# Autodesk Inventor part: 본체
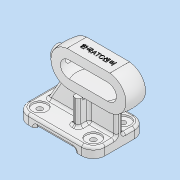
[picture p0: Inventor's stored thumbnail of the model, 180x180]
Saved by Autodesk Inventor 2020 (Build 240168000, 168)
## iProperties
Created: 2025-01
Part Number: 본체
Material: 알루미늄 6061
Document SubType Name: Modeling
Designer: 1강의실14
Density: 2.7 g/cm^3
Appearance: 알루미늄 - 평지
Mass: 359.313 g
Surface Area: 341.872 cm^2
Volume: 133.079 cm^3
Author: 1강의실14
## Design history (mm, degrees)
sketch "스케치1"
  geometry: L1 (-26, 21)-(26, 21); L2 (26, 21)-(26, -21); L3 (26, -21)-(-26, -21); L4 (-26, -21)-(-26, 21); L5 (-26, 10)-(26, 10); L6 (-26, -10)-(26, -10); L7 (0, -29.4)-(0, 29.4) reference; A1 r 21 centre (26, 0) between (26, -21) and (26, 21); A2 r 21 centre (-26, 0) between (-26, 21) and (-26, -21); A3 r 10 centre (-26, 0) between (-26, 10) and (-26, -10); A4 r 10 centre (26, 0) between (26, -10) and (26, 10); 1 further point
  constraints: 12 end point, 8 point on circle, 4 centre point, 4 point on line, 2 coincident, 2 parallel, 1 horizontal, 1 perpendicular
  dimensions: "d0" = 52 distance between parallel lines of L2 L4; "d1" = 42 distance between parallel lines of L3 L1; "d2" = 21 distance from line of point (0, 0) L1; "d3" = 26 distance from line of L4 point (0, 0); "d7" = 26 distance of A1.centre point (0, 0); "d8" = 26 distance of A2.centre point (0, 0); "d10" = 10 radius of A3; "d11" = 10 radius of A4
extrude "돌출2" new body sketch "스케치1" stored distance "d15" = 24; taper "d16" = 0 deg
revolve "회전1" stored, may be unused: angle "d17" = 90 deg
sketch "스케치3"
  geometry: L1 (-42.994, 65.875)-(110.557, 65.875); L2 (110.557, 65.875)-(110.557, 23.891); L3 (110.557, 23.891)-(-42.994, 23.891); L4 (-42.994, 23.891)-(-42.994, 65.875); 1 further point
  constraints: 8 end point, 2 parallel, 1 horizontal, 1 perpendicular
  dimensions: "d18" = 53.87491 distance from line of L1 point (23.065, 12); "d19" = 87.49168 distance from line of L2 point (23.065, 12); "d20" = 153.55083 distance between parallel lines of L2 L4; "d21" = 41.98426 distance between parallel lines of L1 L3
extrude "돌출3" cut sketch "스케치3" extent not by distance; stored distance "d22" = 0; taper "d23" = 0 deg
node "작업 평면1"
sketch "스케치2"
  geometry: L1 (67, -32)-(-26, -32); L2 (-26, -32)-(-26, 32); L3 (-26, 32)-(67, 32); L4 (67, 32)-(67, -32); L5 (-26, 11.891)-(-26, 11.891) reference; L6 (-26, 0)-(-26, 11.891) reference; L7 (-26, -11.891)-(-26, 0) reference; L8 (-26, -11.891)-(-26, -11.891) reference; L9 (-26, 0)-(-26, -11.891) reference; L10 (-26, 11.891)-(-26, 0) reference; 1 further point
  constraints: 8 end point, 2 parallel, 1 horizontal, 1 perpendicular
  dimensions: "d24" = 64 distance between parallel lines of L3 L1; "d25" = 93 distance between parallel lines of L4 L2; "d26" = 32 distance from line of L1 point (0, 0); "d27" = 26 distance from line of L2 point (0, 0)
extrude "돌출4" join sketch "스케치2" distance "d28" = 12; taper "d29" = 0 deg
sketch "스케치4"
  geometry: L1 (0, 0)-(93, 0) reference; L2 (22, 0)-(22, 3); L3 (22, 3)-(71, 3); L4 (71, 3)-(71, 0); L5 (0, 0)-(0, 12) reference; L6 (93, 0)-(93, 12) reference; 1 further point
  constraints: 6 end point, 2 perpendicular, 2 point on line, 1 vertical
  dimensions: "d30" = 22 distance between parallel lines of L5 L2; "d31" = 22 distance between parallel lines of L6 L4; "d32" = 3 distance between parallel lines of L1 L3
extrude "돌출5" cut sketch "스케치4" extent not by distance; stored distance "d33" = 0; taper "d34" = 0 deg
sketch "스케치5"
  geometry: L1 (-15, 17)-(-7, 17); L2 (-7, 17)-(-7, -17); L3 (-7, -17)-(-15, -17); L4 (-15, -17)-(-15, 17); L5 (26, -32)-(26, 32) reference; L6 (-7, 4)-(26, 4); L7 (-7, -4)-(26, -4); 1 further point
  constraints: 12 end point, 4 point on line, 3 perpendicular, 2 parallel, 1 horizontal
  dimensions: "d35" = 8 distance between parallel lines of L2 L4; "d36" = 33 distance between parallel lines of L2 L5; "d37" = 34 distance between parallel lines of L3 L1; "d38" = 17 distance from line of L1 point (0, 0); "d39" = 8 distance between parallel lines of L7 L6; "d40" = 4 distance from line of L6 point (0, 0)
extrude "돌출6" join sketch "스케치5" stored distance "d41" = 12; taper "d42" = 0 deg
sketch "스케치6"
  geometry: L1 (-26, 21)-(-26, 20.84) reference; L2 (26, 21)-(-26, 21) reference; L3 (26, 20.84)-(26, 21) reference; L4 (26, -21)-(26, -20.84) reference; L5 (-7, -21)-(26, -21) reference; L6 (-15, -21)-(-7, -21) reference; L7 (-26, -21)-(-15, -21) reference; L8 (-26, -20.84)-(-26, -21) reference; L9 (-23.122, 10)-(23.122, 10) reference; L10 (23.122, -10)-(-23.122, -10) reference; L11 (4, -63)-(4, -60) reference; L12 (4, -60)-(-45, -60) reference; L13 (-45, -60)-(-45, -63) reference; L14 (-45, -63)-(-67, -63) reference; L15 (-67, -63)-(-67, -51) reference; L16 (26, -51)-(-67, -51) reference; L17 (26, -63)-(26, -51) reference; L18 (26, -63)-(4, -63) reference; L19 (-38.358, -16.979)-(-58, -51); L20 (26, -51)-(-67, -51) reference; A1 r 21 centre (-26, 0) between (-26, 21) and (-26, -21) reference; 1 further point
  constraints: 4 vertical alignment, 2 end point, 1 point on circle, 1 point on line
  dimensions: "d43" = 9 distance from line of L15 L19.end; "d44" = 60 deg angle of L19 L16
feature "리브1" sketch "스케치6" dims "d45" = 1, "d46" = 8, "d47" = 0, "d48" = 0, "d49" = 1, "d50" = 1
sketch "스케치7"
  geometry: L1 (-53, 18)-(12, 18); L2 (12, 18)-(12, -18); L3 (12, -18)-(-53, -18); L4 (-53, -18)-(-53, 18); L5 (26, -32)-(26, 32) reference; 1 further point
  constraints: 8 end point, 2 parallel, 1 horizontal, 1 perpendicular
  dimensions: "d51" = 36 distance between parallel lines of L3 L1; "d52" = 65 distance between parallel lines of L2 L4; "d53" = 18 distance from line of L1 point (0, 0); "d55" = 14 distance between parallel lines of L2 L5
hole "구멍1" sketch "스케치7" at (12, -18), (12, 18), (-53, 18), (-53, -18) diameter "d56" = 6.6; stored, may be unused: countersink angle "d60" = 90 deg, drill point angle "d62" = 0 deg; dims "d57" = 6, "d58" = 18, "d59" = 2, "d61" = 12
sketch "스케치8"
  geometry: L1 (-26, 0)-(-50, 0); A1 r 21 centre (-26, 0) between (-26, 21) and (-38.358, -16.979) reference; 1 further point
  constraints: 2 end point, 1 horizontal
  dimensions: "d64" = 24 distance of L1.start L1.end
node "작업 평면2"
sketch "스케치9"
  geometry: C1 r 8 at (0, 0); 1 further point
  constraints: 1 centre point, 1 coincident
  dimensions: "d66" = 16 diameter of C1
extrude "돌출7" join sketch "스케치9" distance "d67" = 12; taper "d68" = 0 deg
sketch "스케치10"
  geometry: 2 further points
  constraints: 1 coincident
hole "구멍2" sketch "스케치10" at (0, 0) diameter "d69" = 9; stored, may be unused: countersink angle "d73" = 90 deg, drill point angle "d75" = 0 deg; dims "d70" = 6, "d71" = 18, "d72" = 2, "d74" = 16
sketch "스케치11"
  geometry: L1 (52, -11.891)-(52, 0) reference; 2 further points
  constraints: 1 coincident, 1 other
  dimensions: "d76" = 26 distance from line of point (26, -11.891) L1
feature "엠보싱1" sketch "스케치11" dims "d0" = 52, "d1" = 42, "d2" = 21, "d3" = 26, "d7" = 26, "d8" = 26, "d10" = 10, "d11" = 10, "d77" = 0.5, "d78" = 0
fillet "모깎기1" dims "d79" = 3
fillet "모깎기2" dims "d80" = 14
fillet "모깎기3" dims "d81" = 3
fillet "모깎기4" dims "d82" = 3
fillet "모깎기5" dims "d83" = 3
fillet "모깎기6" dims "d84" = 3
fillet "모깎기8" dims "d86" = 3
node "솔리드2"
mirror "미러1"
node "투영된 루프2"
node "투영된 루프3"
node "투영된 루프4"
feature "A9D066F2-1C7D-4E18-AEED-F7BC21143FA4" dims "d56" = 6.6, "d57" = 6, "d58" = 18, "d59" = 2, "d60" = 90 deg, "d61" = 12, "d62" = 0
other parameters: "d14" = -63
